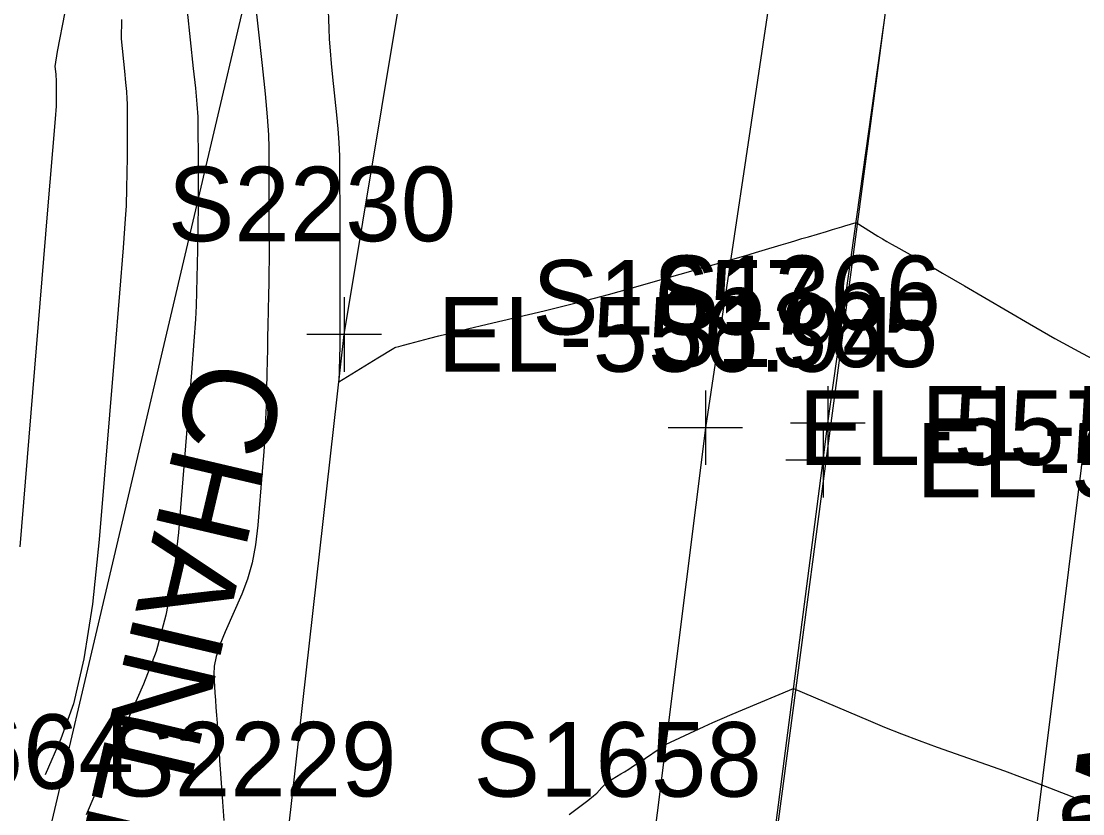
# Model space of a CAD drawing. Extents: x 1724534 to 1727318, y 657156 to 660047.
# Drawn here: x 1725392.5 to 1725449.4, y 658852.2 to 658894.7 of the extents above; entities that cross this region are included whole.
import ezdxf

# ---------------------------------------------------------------- set-up
doc = ezdxf.new("R2010")
doc.units = 0
for name, color, linetype in [('SURVEY - CENTERLINE - Preliminary Text', 7, 'Continuous'), ('SURVEY - CONTOURS - Index with Text', 7, 'Continuous'), ('SURVEY - CONTOURS - Intermediate with optional Text', 7, 'Continuous'), ('SURVEY - DRAINAGE - Area Shapes', 7, 'Continuous'), ('SURVEY - DTM - Breaklines', 7, 'Continuous'), ('SURVEY - DTM - Breaklines - Points - Elevations', 7, 'Continuous'), ('SURVEY - DTM - Breaklines - Points - Locators', 7, 'Continuous'), ('SURVEY - DTM - Breaklines - Points - Numbers', 7, 'Continuous'), ('SURVEY - NON-TRANSPORTATION - Features', 7, 'Continuous'), ('SURVEY - NON-TRANSPORTATION - Features - Points - Numbers', 7, 'Continuous'), ('SURVEY - NON-TRANSPORTATION - Features Text', 7, 'Continuous'), ('SURVEY - TRAFFIC CONTROL - Pavement Marking with Text', 7, 'Continuous'), ('SURVEY - TRANSPORTATION - Features', 7, 'Continuous'), ('SURVEY - TRANSPORTATION - Features - Points - Elevations', 7, 'Continuous'), ('SURVEY - TRANSPORTATION - Features - Points - Locators', 7, 'Continuous'), ('SURVEY - TRANSPORTATION - Features - Points - Numbers', 7, 'Continuous'), ('SURVEY - TRANSPORTATION - Roads', 7, 'Continuous'), ('SURVEY - TRANSPORTATION - Roads - Points - Elevations', 7, 'Continuous'), ('SURVEY - TRANSPORTATION - Roads - Points - Locators', 7, 'Continuous'), ('SURVEY - TRANSPORTATION - Roads - Points - Numbers', 7, 'Continuous')]:
    doc.layers.add(name, color=color, linetype=linetype)

msp = doc.modelspace()

# ---------------------------------------------------------------- linework, layer by layer
at = {"layer": 'SURVEY - CONTOURS - Index with Text'}
msp.add_lwpolyline([(1725397.862, 658894.785), (1725397.827, 658893.745), (1725398.015, 658892.001), (1725398.076, 658891.402), (1725398.121, 658890.911), (1725398.147, 658890.529), (1725398.157, 658890.256), (1725398.162, 658887.868), (1725398.157, 658887.381), (1725398.12, 658885.725), (1725398.099, 658884.773), (1725398.055, 658884.08), (1725397.936, 658882.521), (1725397.742, 658880.095), (1725397.473, 658876.804), (1725396.655, 658866.873), (1725396.296, 658863.411), (1725395.834, 658860.473), (1725395.269, 658858.06), (1725394.599, 658856.172), (1725393.75, 658854.255)], dxfattribs=at)
at = {"layer": 'SURVEY - CONTOURS - Intermediate with optional Text'}
for points in [[(1725404.925, 658896.713), (1725405.4, 658892.307), (1725405.556, 658890.792), (1725405.667, 658889.552), (1725405.735, 658888.587), (1725405.758, 658887.896), (1725405.762, 658886.42), (1725405.763, 658885.86), (1725405.765, 658885.286), (1725405.766, 658884.698), (1725405.768, 658884.096), (1725405.772, 658882.473), (1725405.771, 658881.863), (1725405.767, 658881.249), (1725405.759, 658880.632), (1725405.747, 658880.012), (1725405.709, 658878.354), (1725405.695, 658877.728), (1725405.681, 658877.093), (1725405.666, 658876.449), (1725405.651, 658875.796), (1725405.612, 658874.043), (1725405.588, 658873.332), (1725405.545, 658872.512), (1725405.483, 658871.584), (1725405.402, 658870.547), (1725405.163, 658867.638), (1725405.042, 658866.589), (1725404.86, 658865.624), (1725404.617, 658864.742), (1725404.313, 658863.944), (1725403.419, 658861.928), (1725403.129, 658861.219), (1725402.929, 658860.604), (1725402.82, 658860.083), (1725402.801, 658859.655), (1725402.87, 658858.641), (1725402.896, 658858.255), (1725402.923, 658857.857), (1725402.951, 658857.448), (1725402.98, 658857.027), (1725403.058, 658855.889), (1725403.087, 658855.456), (1725403.118, 658855.009), (1725403.149, 658854.548), (1725403.182, 658854.073), (1725403.269, 658852.79), (1725403.303, 658852.3), (1725403.337, 658851.794)], [(1725408.925, 658895.729), (1725408.974, 658894.29), (1725409.001, 658893.723), (1725409.043, 658893.101), (1725409.101, 658892.425), (1725409.175, 658891.694), (1725409.392, 658889.673), (1725409.464, 658888.92), (1725409.516, 658888.176), (1725409.547, 658887.441), (1725409.559, 658886.716), (1725409.566, 658884.065), (1725409.567, 658883.318), (1725409.569, 658882.552), (1725409.571, 658881.768), (1725409.577, 658879.655), (1725409.577, 658878.91), (1725409.575, 658878.262), (1725409.57, 658877.709), (1725409.562, 658877.251), (1725409.519, 658875.342), (1725411.616, 658876.63), (1725412.461, 658877.148), (1725412.519, 658877.183), (1725412.578, 658877.198), (1725412.729, 658877.238), (1725412.979, 658877.303), (1725413.328, 658877.394), (1725414.392, 658877.672), (1725414.884, 658877.797), (1725415.563, 658877.964), (1725416.428, 658878.172), (1725417.48, 658878.423), (1725420.535, 658879.147), (1725421.681, 658879.426), (1725422.831, 658879.719), (1725423.983, 658880.026), (1725425.138, 658880.348), (1725430.534, 658881.882), (1725431.363, 658882.124), (1725431.594, 658882.192), (1725431.884, 658882.278), (1725432.233, 658882.383), (1725433.245, 658882.686), (1725433.622, 658882.799), (1725433.994, 658882.91), (1725434.361, 658883.02), (1725434.723, 658883.127), (1725435.682, 658883.413), (1725436.013, 658883.511), (1725436.503, 658883.658), (1725436.663, 658883.706), (1725437.273, 658883.893), (1725438.44, 658883.16), (1725438.688, 658883.007), (1725438.931, 658882.863), (1725439.168, 658882.727), (1725439.401, 658882.598), (1725440.015, 658882.268), (1725440.38, 658882.064), (1725441.015, 658881.699), (1725441.919, 658881.174), (1725443.094, 658880.488), (1725446.585, 658878.446), (1725447.947, 658877.667), (1725449.415, 658876.862), (1725450.988, 658876.03)], [(1725394.807, 658895.169), (1725394.402, 658893.066), (1725394.278, 658892.261), (1725394.322, 658891.849), (1725394.337, 658891.707), (1725394.347, 658891.59), (1725394.353, 658891.5), (1725394.356, 658891.435), (1725394.356, 658890.813), (1725394.342, 658890.138), (1725394.289, 658889.454), (1725393.872, 658884.351), (1725392.401, 658866.49)], [(1725401.376, 658895.229), (1725401.707, 658892.154), (1725401.816, 658891.097), (1725401.894, 658890.231), (1725401.941, 658889.558), (1725401.957, 658889.076), (1725401.962, 658887.254), (1725401.967, 658885.291), (1725401.966, 658884.865), (1725401.963, 658884.437), (1725401.958, 658884.007), (1725401.923, 658882.417), (1725401.855, 658879.408), (1725401.821, 658878.706), (1725401.74, 658877.516), (1725401.613, 658875.84), (1725401.438, 658873.676), (1725400.909, 658867.255), (1725400.643, 658864.94), (1725400.241, 658862.81), (1725399.705, 658860.864), (1725399.033, 658859.103), (1725397.06, 658854.654), (1725396.414, 658853.183), (1725395.954, 658852.106)], [(1725421.878, 658852.119), (1725422.45, 658852.538), (1725422.887, 658852.87), (1725423.189, 658853.114), (1725423.357, 658853.27), (1725423.623, 658853.568), (1725423.732, 658853.68), (1725423.862, 658853.79), (1725424.011, 658853.899), (1725424.18, 658854.007), (1725424.657, 658854.293), (1725424.852, 658854.412), (1725425.078, 658854.556), (1725425.336, 658854.724), (1725425.626, 658854.916), (1725427.054, 658855.869), (1725429.126, 658856.838), (1725429.588, 658857.05), (1725430.085, 658857.272), (1725430.617, 658857.503), (1725431.184, 658857.743), (1725433.914, 658858.886), (1725437.929, 658857.173), (1725438.805, 658856.808), (1725439.714, 658856.448), (1725440.654, 658856.091), (1725441.627, 658855.738), (1725444.265, 658854.803), (1725445.239, 658854.454), (1725446.182, 658854.109), (1725447.095, 658853.767), (1725447.976, 658853.429), (1725450.287, 658852.532)]]:
    msp.add_lwpolyline(points, dxfattribs=at)
at = {"layer": 'SURVEY - DRAINAGE - Area Shapes'}
msp.add_lwpolyline([(1725413.857, 659016.262), (1725457.865, 659006.777), (1725450.771, 658971.313), (1725440.158, 658905.178), (1725430.327, 658830.786), (1725434.818, 658762.279), (1725443.395, 658712.742), (1725438.076, 658666.381), (1725439.858, 658660.363), (1725446.978, 658655.619), (1725466.254, 658652.836), (1725462.782, 658619.36), (1725332.114, 658635.492), (1725320.808, 658709.212), (1725296.636, 658734.956), (1725279.099, 658753.634), (1725289.919, 658934.648), (1725297.605, 659050.843)], close=True, dxfattribs=at)
at = {"layer": 'SURVEY - DTM - Breaklines'}
msp.add_lwpolyline([(1725406.449, 658848.086), (1725409.805, 658877.882), (1725414.842, 658908.26), (1725416.621, 658909.953)], dxfattribs=at)
at = {"layer": 'SURVEY - DTM - Breaklines - Points - Locators'}
for p, q in [((1725409.805, 658879.882), (1725409.805, 658875.882)), ((1725411.805, 658877.882), (1725407.805, 658877.882))]:
    msp.add_line(p, q, dxfattribs=at)
at = {"layer": 'SURVEY - NON-TRANSPORTATION - Features'}
msp.add_lwpolyline([(1725357.678, 658691.928), (1725363.165, 658711.31), (1725369.342, 658739.883), (1725375.283, 658769.307), (1725379.116, 658784.738), (1725384.76, 658809.108), (1725393.359, 658848.496), (1725405.647, 658900.795), (1725418.141, 658956.869), (1725428.713, 659003.816), (1725429.417, 659007.151)], dxfattribs=at)
at = {"layer": 'SURVEY - TRAFFIC CONTROL - Pavement Marking with Text'}
msp.add_lwpolyline([(1725460.313, 658957.642), (1725453.259, 658902.135), (1725452.764, 658898.17), (1725443.879, 658826.783), (1725443.64, 658824.8), (1725439.422, 658789.083), (1725439.193, 658787.097), (1725436.275, 658761.27), (1725433.358, 658735.444), (1725431.642, 658719.312)], dxfattribs=at)
at = {"layer": 'SURVEY - TRANSPORTATION - Features'}
msp.add_lwpolyline([(1725434.197, 658921.722), (1725432.895, 658897.637), (1725429.184, 658872.875), (1725426.078, 658848.074), (1725422.871, 658823.298), (1725419.935, 658798.442), (1725416.678, 658773.894), (1725414.767, 658758.792), (1725412.806, 658748.879), (1725411.089, 658739.694), (1725408.931, 658729.883), (1725406.226, 658721.074), (1725404.106, 658715.945), (1725401.338, 658711.361), (1725398.637, 658706.683), (1725395.192, 658702.159), (1725391.101, 658697.729), (1725387.348, 658693.004), (1725382.763, 658689.258), (1725380.992, 658687.831)], dxfattribs=at)
at = {"layer": 'SURVEY - TRANSPORTATION - Features - Points - Locators'}
for p, q in [((1725429.184, 658874.875), (1725429.184, 658870.875)), ((1725431.184, 658872.875), (1725427.184, 658872.875))]:
    msp.add_line(p, q, dxfattribs=at)
at = {"layer": 'SURVEY - TRANSPORTATION - Roads'}
msp.add_lwpolyline([(1725423.519, 658775.953), (1725428.836, 658819.598), (1725429.085, 658821.581), (1725435.499, 658871.131), (1725435.76, 658873.112), (1725439.371, 658898.842), (1725439.657, 658900.819), (1725445.023, 658936.389), (1725447.926, 658954.139)], dxfattribs=at)
at = {"layer": 'SURVEY - TRANSPORTATION - Roads - Points - Locators'}
for p, q in [((1725435.76, 658875.112), (1725435.76, 658871.112)), ((1725437.76, 658873.112), (1725433.76, 658873.112)), ((1725435.499, 658873.131), (1725435.499, 658869.131)), ((1725437.499, 658871.131), (1725433.499, 658871.131))]:
    msp.add_line(p, q, dxfattribs=at)

# ---------------------------------------------------------------- texts
at = {"layer": 'SURVEY - CENTERLINE - Preliminary Text'}
msp.add_text('S 7%%d 12\' 53" W', height=6, rotation=262.7854, dxfattribs=at).set_placement((1725454.913, 658900.789))
at = {"layer": 'SURVEY - DTM - Breaklines - Points - Elevations'}
msp.add_text('EL-556.94', height=4, dxfattribs=at).set_placement((1725414.805, 658875.882))
at = {"layer": 'SURVEY - DTM - Breaklines - Points - Numbers'}
for s, p in [('S2230', (1725400.344, 658882.882)), ('S2229', (1725397.146, 658853.086))]:
    msp.add_text(s, height=4, dxfattribs=at).set_placement(p)
at = {"layer": 'SURVEY - NON-TRANSPORTATION - Features - Points - Numbers'}
msp.add_text('S664', height=4, dxfattribs=at).set_placement((1725386.023, 658853.496))
at = {"layer": 'SURVEY - NON-TRANSPORTATION - Features Text'}
msp.add_text('CHAINLINK', height=5, rotation=256.7844, dxfattribs=at).set_placement((1725401.816, 658876.778))
at = {"layer": 'SURVEY - TRANSPORTATION - Features - Points - Elevations'}
msp.add_text('EL-557.36', height=4, dxfattribs=at).set_placement((1725434.184, 658870.875))
at = {"layer": 'SURVEY - TRANSPORTATION - Features - Points - Numbers'}
for s, p in [('S1657', (1725419.896, 658877.875)), ('S1658', (1725416.743, 658853.074))]:
    msp.add_text(s, height=4, dxfattribs=at).set_placement(p)
at = {"layer": 'SURVEY - TRANSPORTATION - Roads - Points - Elevations'}
for s, p in [('EL-557.43', (1725440.76, 658871.112)), ('EL-557.51', (1725440.499, 658869.131))]:
    msp.add_text(s, height=4, dxfattribs=at).set_placement(p)
at = {"layer": 'SURVEY - TRANSPORTATION - Roads - Points - Numbers'}
for s, p in [('S1366', (1725426.362, 658878.112)), ('S1365', (1725426.211, 658876.131)), ('S1546', (1725447.914, 658849.112))]:
    msp.add_text(s, height=4, dxfattribs=at).set_placement(p)

doc.saveas('drawing.dxf')
